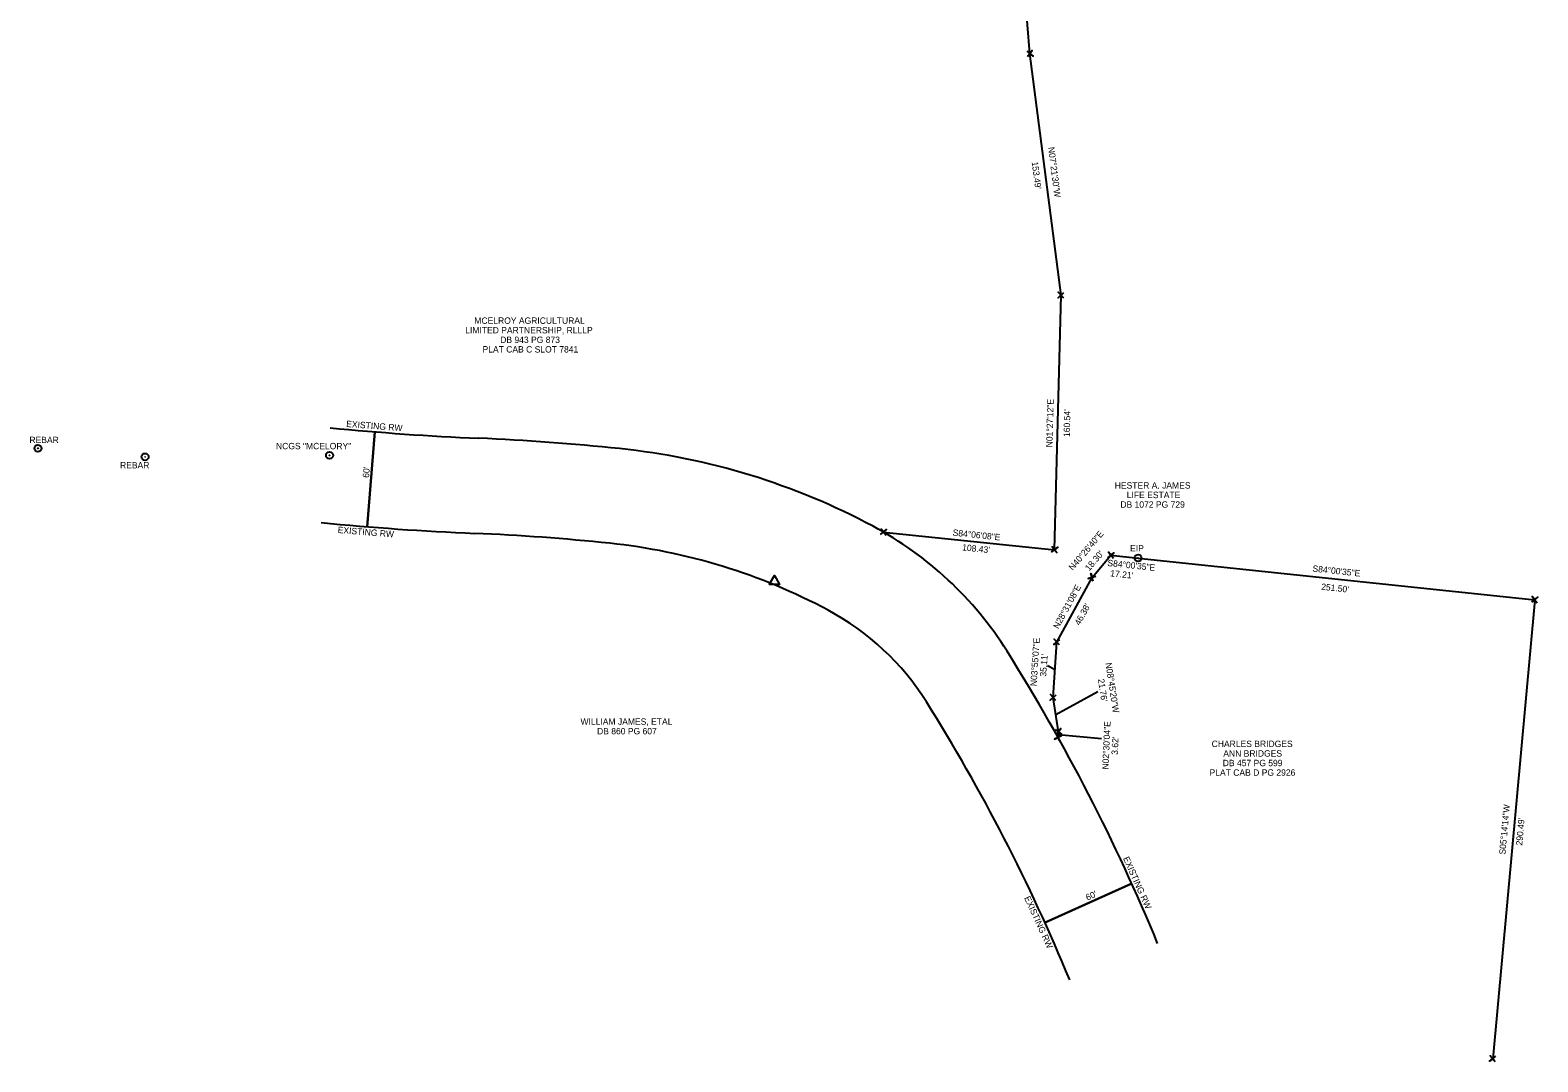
# Model space of a CAD drawing. Extents: x 841463 to 842414, y 701018 to 702296.
# Drawn here: x 841463 to 842414, y 701018 to 701668 of the extents above; entities that cross this region are included whole.
import ezdxf

# ---------------------------------------------------------------- set-up
doc = ezdxf.new("R2010")
doc.units = 0
for name, color, linetype in [('Exist Property Corner CELL', 7, 'Continuous'), ('Exist Property Iron Pin CELL', 7, 'Continuous'), ('Exist Property Line', 7, 'Continuous'), ('Exist Property Text', 7, 'Continuous'), ('Exist Right of Way Line', 7, 'Continuous'), ('Exist Right of Way Monument CELL', 7, 'Continuous'), ('Exist Right of Way Text', 7, 'Continuous')]:
    doc.layers.add(name, color=color, linetype=linetype)

msp = doc.modelspace()

# ---------------------------------------------------------------- linework, layer by layer
at = {"layer": 'Exist Property Corner CELL'}
for p, q in [((842093.47, 701653.27), (842093.47, 701653.27)), ((842113.13, 701501.04), (842113.13, 701501.04)), ((842001.2, 701351.7), (842001.2, 701351.7)), ((842109.06, 701340.55), (842109.06, 701340.55)), ((842144.55, 701337.15), (842144.55, 701337.15)), ((842132.67, 701323.22), (842132.67, 701323.22)), ((842411.79, 701309.1), (842411.79, 701309.1)), ((842110.53, 701282.47), (842110.53, 701282.47)), ((842108.13, 701247.44), (842108.13, 701247.44)), ((842111.28, 701222.32), (842111.28, 701222.32)), ((842111.44, 701225.94), (842111.44, 701225.94)), ((842385.27, 701019.83), (842385.27, 701019.83))]:
    msp.add_line(p, q, dxfattribs=at)
for points in [[(842091.49, 701654.8), (842095.45, 701651.74), (842093.47, 701653.27), (842095, 701655.25), (842091.95, 701651.29)], [(842114.85, 701499.23), (842111.41, 701502.85), (842113.13, 701501.04), (842111.32, 701499.32), (842114.94, 701502.76)], [(841999.26, 701350.12), (842003.14, 701353.27), (842001.2, 701351.7), (841999.63, 701353.64), (842002.78, 701349.75)], [(842107.12, 701338.98), (842111, 701342.13), (842109.06, 701340.55), (842107.48, 701342.49), (842110.64, 701338.61)], [(842142.6, 701335.57), (842146.49, 701338.72), (842144.55, 701337.15), (842142.97, 701339.09), (842146.12, 701335.2)], [(842133.38, 701320.82), (842131.97, 701325.62), (842132.67, 701323.22), (842130.28, 701322.51), (842135.07, 701323.93)], [(842409.84, 701307.53), (842413.73, 701310.68), (842411.79, 701309.1), (842410.22, 701311.05), (842413.36, 701307.16)], [(842112.17, 701280.58), (842108.89, 701284.35), (842110.53, 701282.47), (842108.64, 701280.83), (842112.41, 701284.11)], [(842109.77, 701245.55), (842106.49, 701249.32), (842108.13, 701247.44), (842106.25, 701245.8), (842110.02, 701249.08)], [(842109.43, 701227.42), (842113.46, 701224.46), (842111.44, 701225.94), (842112.92, 701227.95), (842109.96, 701223.92)], [(842112.42, 701220.09), (842110.15, 701224.54), (842111.28, 701222.32), (842109.06, 701221.18), (842113.51, 701223.46)], [(842386.87, 701017.9), (842383.67, 701021.75), (842385.27, 701019.83), (842383.35, 701018.23), (842387.19, 701021.42)]]:
    msp.add_lwpolyline(points, dxfattribs=at)
at = {"layer": 'Exist Property Iron Pin CELL'}
for centre, radius in [((841468.1, 701404.52), 2.2), ((841468.1, 701404.52), 0.0707), ((841535.67, 701399.14), 2.2), ((841535.67, 701399.14), 0.0707), ((841651.93, 701400.1), 2.2), ((841651.93, 701400.1), 0.0707), ((842161.66, 701335.35), 2.2), ((842161.66, 701335.35), 0.0707)]:
    msp.add_circle(centre, radius, dxfattribs=at)
at = {"layer": 'Exist Property Line'}
for p, q in [((842093.47, 701653.27), (842069.7, 701941.91)), ((842113.13, 701501.04), (842093.47, 701653.27)), ((842109.06, 701340.55), (842113.13, 701501.04)), ((842001.2, 701351.7), (842109.06, 701340.55)), ((842132.67, 701323.22), (842144.55, 701337.15)), ((842144.55, 701337.15), (842161.66, 701335.35)), ((842161.66, 701335.35), (842411.79, 701309.1)), ((842110.53, 701282.47), (842132.67, 701323.22)), ((842411.79, 701309.1), (842385.27, 701019.83)), ((842108.13, 701247.44), (842110.53, 701282.47)), ((842111.44, 701225.94), (842108.13, 701247.44)), ((842111.28, 701222.32), (842111.44, 701225.94)), ((842111.28, 701222.32), (842111.77, 701223.82))]:
    msp.add_line(p, q, dxfattribs=at)
at = {"layer": 'Exist Property Text'}
for p, q in [((842109.33, 701264.95), (842104.52, 701267.51)), ((842109.79, 701236.69), (842136.41, 701251.26)), ((842111.36, 701224.13), (842138.73, 701221.64))]:
    msp.add_line(p, q, dxfattribs=at)
at = {"layer": 'Exist Right of Way Line'}
for centre, radius, start, end in [((841819.3, 703119.3), 1710, 264.39928, 267.54402), ((841683.67, 699957.21), 1455, 84.03827, 87.54402), ((841789.61, 700971.69), 435, 61.88711, 84.03827), ((841819.3, 703119.3), 1770, 264.39928, 267.54402), ((841888.57, 701156.92), 225, 32.15177, 61.88711), ((841683.67, 699957.21), 1395, 84.03827, 87.54402), ((841789.61, 700971.69), 375, 61.88711, 84.03827), ((841888.57, 701156.92), 165, 32.15177, 61.88711), ((841046.16, 700627.42), 1220, 22.40796, 32.15177), ((841046.16, 700627.42), 1160, 22.40796, 32.15177)]:
    msp.add_arc(centre, radius, start, end, dxfattribs=at)
at = {"layer": 'Exist Right of Way Monument CELL'}
msp.add_line((841932.39, 701320.68), (841932.39, 701320.68), dxfattribs=at)
msp.add_lwpolyline([(841929.14, 701318.79), (841932.39, 701324.43), (841935.63, 701318.79)], close=True, dxfattribs=at)
at = {"layer": 'Exist Right of Way Text'}
for p, q in [((841680.52, 701414.94), (841675.65, 701355.14)), ((841675.65, 701355.14), (841680.52, 701414.94)), ((842157.67, 701130.34), (842103.01, 701105.61)), ((842103.01, 701105.61), (842157.67, 701130.34))]:
    msp.add_line(p, q, dxfattribs=at)

# ---------------------------------------------------------------- texts
at = {"layer": 'Exist Property Text'}
for s, rotation, p in [('N07°21\'30"W', 277.35833, (842104.92, 701594.17)), ("153.49'", 277.35833, (842094.6, 701584.97)), ('N01°27\'12"E', 88.54667, (842107.7, 701405.1)), ("160.54'", 88.54667, (842118.67, 701411.61)), ('S84°06\'08"E', 354.10222, (842044.63, 701349.52)), ('N40°26\'40"E', 49.55556, (842120.55, 701327.24)), ("108.43'", 354.10222, (842050.63, 701340.23)), ("18.30'", 49.55556, (842130.91, 701326.87)), ('S84°00\'35"E', 354.00972, (842142.2, 701330.39)), ("17.21'", 354.00972, (842144.02, 701323.87)), ('S84°00\'35"E', 354.00972, (842271.5, 701326.84)), ('N28°31\'08"E', 61.48111, (842111.43, 701290.41)), ("251.50'", 354.00972, (842276.97, 701315.41)), ("46.38'", 61.48111, (842124.91, 701292.59)), ('N03°55\'07"E', 86.08139, (842097.71, 701254.53)), ("35.11'", 86.08139, (842103.76, 701260.52)), ('N08°45\'20"W', 278.75556, (842141.04, 701269.17)), ("21.76'", 278.75556, (842136.31, 701259.01)), ('N02°30\'04"E', 87.49884, (842143.06, 701202.01)), ("3.62'", 87.49884, (842148.91, 701211.32)), ('S05°14\'14"W', 84.76278, (842393.26, 701148.36)), ("290.49'", 84.76278, (842403.86, 701154.08))]:
    msp.add_text(s, height=4.02, rotation=rotation, dxfattribs=at).set_placement(p)
for s, p in [('MCELROY AGRICULTURAL', (841743.24, 701482.98)), ('LIMITED PARTNERSHIP, RLLLP', (841737.49, 701476.95)), ('DB 943 PG 873', (841759.55, 701470.92)), ('PLAT CAB C SLOT 7841', (841748.39, 701464.89)), ('REBAR', (841462.74, 701407.78)), ('NCGS "MCELORY"', (841618.19, 701403.93)), ('REBAR', (841519.85, 701391.85)), ('HESTER A. JAMES', (842146.97, 701379.16)), ('DB 1072 PG 729', (842150.53, 701367.1)), ('LIFE ESTATE', (842154.57, 701373.13)), ('EIP', (842156.67, 701339.51)), ('WILLIAM JAMES, ETAL', (841810.17, 701230.29)), ('DB 860 PG 607', (841820.6, 701224.26)), ('CHARLES BRIDGES', (842208.08, 701216.27)), ('ANN BRIDGES', (842215.42, 701210.24)), ('PLAT CAB D PG 2926', (842206.76, 701198.18)), ('DB 457 PG 599', (842215.08, 701204.21))]:
    msp.add_text(s, height=4.02, dxfattribs=at).set_placement(p)
at = {"layer": 'Exist Right of Way Text'}
for s, rotation, p in [('EXISTING RW', 355.61626, (841662.34, 701418)), ("60'", 85.34508, (841676.8, 701385.81)), ('EXISTING RW', 355.39423, (841656.98, 701351.2)), ('EXISTING RW', 294.02305, (842152.15, 701146.16)), ("60'", 24.34531, (842129.74, 701119.37)), ('EXISTING RW', 294.55156, (842089.78, 701121.19))]:
    msp.add_text(s, height=4.02, rotation=rotation, dxfattribs=at).set_placement(p)

doc.saveas('drawing.dxf')
